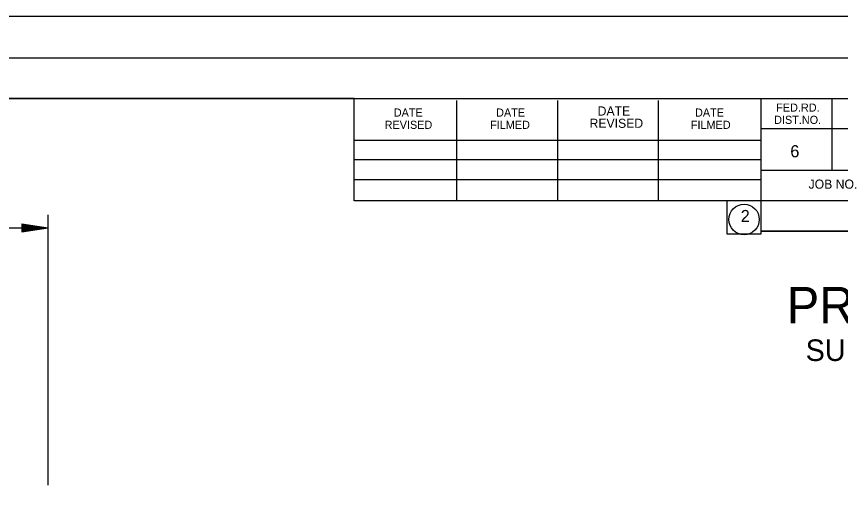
# Model space of a CAD drawing. Extents: x 3575 to 11445, y 9479 to 13278.
# Drawn here: x 5116.4 to 5513.3, y 10877.9 to 11106.1 of the extents above; entities that cross this region are included whole.
import ezdxf

# ---------------------------------------------------------------- set-up
doc = ezdxf.new("R2010")
doc.units = 0
for name, color, linetype in [('_Drafting 1', 7, 'Continuous'), ('R_NoPlot', 7, 'Continuous'), ('STAMP_PE_CRAFTON-SIGNATURE', 7, 'Continuous'), ('STAMP_PE_SEAL-INFO', 7, 'Continuous'), ('STAMP_PRELIMINARY', 7, 'Continuous')]:
    doc.layers.add(name, color=color, linetype=linetype)

msp = doc.modelspace()

# ---------------------------------------------------------------- linework, layer by layer
at = {"layer": '_Drafting 1'}
msp.add_lwpolyline([(4109.53, 11066.7), (4109.53, 10039.4), (5690.43, 10039.4), (5690.43, 11002.7), (5474.93, 11002.7), (5474.93, 11001.26), (5458.74, 11001.26), (5458.74, 11017.3), (5279.13, 11017.3), (5279.13, 11066.7)], close=True, dxfattribs=at)
at = {"layer": 'R_NoPlot'}
msp.add_lwpolyline([(4047.49, 11086.17), (5714.19, 11086.17), (5714.19, 10019.49), (4047.49, 10019.49)], close=True, dxfattribs=at)
at = {"layer": 'STAMP_PE_CRAFTON-SIGNATURE'}
for p, q in [((5131.61, 10880.48), (5131.61, 11010.63)), ((4490.54, 11004.34), (5131.61, 11004.34)), ((5119.01, 11006.22), (5131.61, 11004.34)), ((5119.01, 11006.22), (5119.01, 11002.45)), ((5119.01, 11005.94), (5129.5, 11004.34)), ((5119.01, 11005.61), (5127.33, 11004.34)), ((5119.01, 11005.29), (5125.24, 11004.34)), ((5119.01, 11004.97), (5123.11, 11004.34)), ((5119.01, 11004.64), (5121.03, 11004.34)), ((5119.01, 11002.45), (5131.61, 11004.34)), ((5119.01, 11003.75), (5123.11, 11004.34)), ((5119.01, 11003.1), (5127.33, 11004.34)), ((5119.01, 11002.77), (5129.5, 11004.34)), ((5119.01, 11003.41), (5125.24, 11004.34)), ((5119.01, 11004.04), (5121.03, 11004.34))]:
    msp.add_line(p, q, dxfattribs=at)
at = {"layer": 'STAMP_PRELIMINARY'}
for p, q in [((5713.43, 11106.1), (3953.43, 11106.1)), ((4109.53, 11066.7), (5690.43, 11066.7)), ((5279.13, 11017.3), (5279.13, 11066.7)), ((5474.93, 11066.7), (5474.93, 11002.7)), ((5509.13, 11066.7), (5509.13, 11032)), ((5328.43, 11017.3), (5328.43, 11065.7)), ((5377.23, 11017.3), (5377.23, 11065.7)), ((5425.63, 11017.3), (5425.63, 11065.7)), ((5690.43, 11052), (5474.93, 11052)), ((5279.13, 11046.6), (5474.93, 11046.6)), ((5279.13, 11037.3), (5474.93, 11037.3)), ((5690.43, 11032), (5474.93, 11032)), ((5279.13, 11027.6), (5474.93, 11027.6)), ((5690.43, 11017.3), (5279.13, 11017.3)), ((5474.93, 11002.7), (5690.43, 11002.7))]:
    msp.add_line(p, q, dxfattribs=at)
msp.add_circle((5466.87, 11008.38), 7.33, dxfattribs=at)

# ---------------------------------------------------------------- texts
at = {"layer": 'STAMP_PE_SEAL-INFO'}
for s, height, p in [('PRELIMINARY', 17.5, (5487.46, 10958.41)), ('SUBJECT TO REVISION', 10.3756, (5496.51, 10940.26))]:
    msp.add_text(s, height=height, dxfattribs=at).set_placement(p)
at = {"layer": 'STAMP_PRELIMINARY'}
for s, height, p in [('DATE', 4.396, (5396.33, 11058.4)), ('FED.RD.', 3.91, (5482.33, 11060.3)), ('DATE', 3.91, (5298.13, 11057.9)), ('DATE', 3.91, (5347.43, 11057.9)), ('DATE', 3.91, (5443.23, 11057.9)), ('DIST.NO.', 3.91, (5481.33, 11054.4)), ('REVISED', 3.91, (5293.73, 11052)), ('FILMED', 3.91, (5344.53, 11052)), ('REVISED', 4.396, (5392.43, 11052.5)), ('FILMED', 3.91, (5441.23, 11052)), ('6', 5.86, (5489.13, 11038.3)), ('6', 5.86, (5489.13, 11038.3)), ('JOB NO.', 4.396, (5497.93, 11023.2)), ('2', 5.86, (5465.23, 11007.1))]:
    msp.add_text(s, height=height, dxfattribs=at).set_placement(p)

doc.saveas('drawing.dxf')
